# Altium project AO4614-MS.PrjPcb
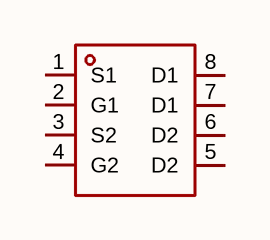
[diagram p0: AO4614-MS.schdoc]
1 sheet, 1 parts. Net scope: global (net labels, ports and power ports of the same name join across sheets).

## Sheet AO4614-MS.schdoc
size 127 x 101 mm

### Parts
Q?  ao4614-ms  [SOP-8_L5.0-W4.0-P1.27-LS6.2-BL]  (value not drawn)

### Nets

Not connected (* = marked no-connect by the designer): Q? 1(S1) 2(G1) 3(S2) 4(G2) 5(D2) 6(D2) 7(D1) 8(D1)

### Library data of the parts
Q? = ao4614-ms: 数量:1个N沟道+1个P沟道;漏源电压(Vdss):40V;连续漏极电流(Id):7.2A；6.5A;导通电阻(RDS(on)):20mΩ@10V；45mΩ@10V;耗散功率(Pd):1.67W;阈值电压(Vgs(th)):2.5V；2.5V;; Manufacturer: MSKSEMI(美森科); AddInBom: yes; ModelId: a3315c1c78f949e6bb82c6eaca1c53c7; ModelName: SOP-8_L5.0-W4.0-H1.8-LS6.2-P1.27; ModelTransform: 244.094,196.85,0,90,0,0,0,0,0; Drain to Source Voltage: 40V; Pd - Power Dissipation: 1.67W; Gate Charge(Qg): 5.5nC@4.5V；11.5nC@4.5V; Input Capacitance(Ciss): 593pF；1.415nF; Reverse Transfer Capacitance (Crss@Vds): 56pF；102pF; Type: N沟道+P沟道; Output Capacitance(Coss): 134pF；76pF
